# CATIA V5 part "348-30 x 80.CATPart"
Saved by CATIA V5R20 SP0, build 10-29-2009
Part number: 348-30 x 80
Definition: NONE
Nomenclature: 348-30 x 80
Source: Unknown
Description: 348-30 x 80
Bounding box of the stored display mesh (mm): x 0 to 80, y -22.5 to 22.5, z -22.5 to 22.5
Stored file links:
  C:\Users\Utente\Desktop\IO LAVORO\3D X SITO CF\X SITO\3D files 348\348-30 x 80.CATPart
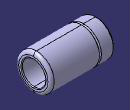
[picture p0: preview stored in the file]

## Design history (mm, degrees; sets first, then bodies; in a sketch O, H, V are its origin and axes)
Body1 "348-30 x 80" (main body)
  Solid1: solid without history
